RoboDK station: M900-600 working.rdk

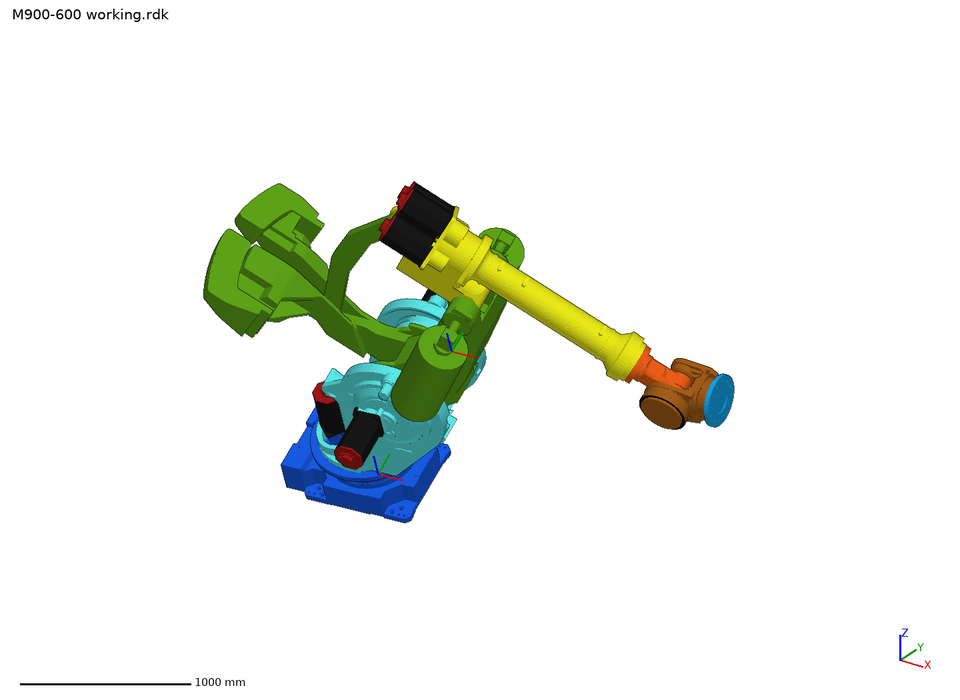
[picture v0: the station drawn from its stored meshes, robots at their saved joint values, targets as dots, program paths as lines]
Station M900-600 working (saved by RoboDK 5.6.0). Poses are relative to the parent item; angles as X-Y-Z fixed-axis rotations.
  - frame Base at (0, 0, 0) mm
    - object M900-600 at (0, 0, 0) mm, geometry from M900-600.IGS
      - item type 7 M900-600-0
      - item type 7 M900-600-1
      - item type 7 M900-600-2
      - item type 7 M900-600-3
      - item type 7 M900-600-4
      - item type 7 M900-600-5
      - item type 7 M900-600-6
      - item type 7 M900-600-7
      - item type 7 M900-600-8
      - item type 7 M900-600-9
      - item type 7 M900-600-10
      - item type 7 M900-600-11
      - item type 7 M900-600-12
      - item type 7 M900-600-13
      - item type 7 M900-600-14
      - item type 7 M900-600-15
      - item type 7 M900-600-16
      - item type 7 M900-600-17
      - item type 7 M900-600-18
      - item type 7 M900-600-19
      - item type 7 M900-600-20
      - item type 7 M900-600-21
      - item type 7 M900-600-22
      - item type 7 M900-600-23
      - item type 7 M900-600-24
      - item type 7 M900-600-25
      - item type 7 M900-600-27
      - item type 7 M900-600-28
      - item type 7 M900-600-29
      - item type 7 M900-600-30
      - item type 7 M900-600-31
      - item type 7 M900-600-32
      - item type 7 M900-600-33
      - item type 7 M900-600-34
      - item type 7 M900-600-35
      - item type 7 M900-600-36
      - item type 7 M900-600-37
      - item type 7 M900-600-38
      - item type 7 M900-600-39
      - item type 7 M900-600-40
      - item type 7 M900-600-41
      - item type 7 M900-600-42
      - item type 7 M900-600-43
      - item type 7 M900-600-44
      - item type 7 M900-600-45
      - item type 7 M900-600-46
      - item type 7 M900-600-47
      - item type 7 M900-600-48
      - item type 7 M900-600-49
      - item type 7 M900-600-50
      - item type 7 M900-600-51
      - item type 7 M900-600-52
      - item type 7 M900-600-53
      - item type 7 M900-600-54
      - item type 7 M900-600-55
      - item type 7 M900-600-56
      - item type 7 M900-600-57
      - item type 7 M900-600-58
      - item type 7 M900-600-59
      - item type 7 M900-600-60
      - item type 7 M900-600-61
      - item type 7 M900-600-62
      - item type 7 M900-600-63
      - item type 7 M900-600-64
      - item type 7 M900-600-65
      - item type 7 M900-600-66
      - item type 7 M900-600-67
      - item type 7 M900-600-68
      - item type 7 M900-600-69
      - item type 7 M900-600-70
      - item type 7 M900-600-71
      - item type 7 M900-600-72
      - item type 7 M900-600-73
      - item type 7 M900-600-74
      - item type 7 M900-600-75
      - item type 7 M900-600-76
      - item type 7 M900-600-77
      - item type 7 M900-600-78
      - item type 7 M900-600-79
      - item type 7 M900-600-80
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      - item type 7 AW: QW | ;W | M900-600-476
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      - item type 7 à': ÿ' | ï' | êÇ | ÿÇ | M900-600-880
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      - item type 7 Ãã: Ãã | M900-600-920
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      - item type 7 ÇE: ÇE | ÇE | M900-600-988
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      - item type 7 èE: èE | èE | M900-600-991
      - item type 7 èE: èE | èE | M900-600-992
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      - item type 7 oE: oE | oE | M900-600-994
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      - item type 7 oE: oE | oE | M900-600-1183
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      - item type 7 oE: oE | oE | oE | oE | oE | M900-600-1188
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      - item type 7 èE: èE | èE | M900-600-1191
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      - item type 7 èE: èE | èE | M900-600-1193
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      - item type 7 ÇE: ÇE | ÇE | M900-600-1210
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      - item type 7 Ã7: Ã7 | Ã7 | Ã7 | M900-600-1705
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      - item type 7 øw: øw | C7 | C7 | C7 | C7 | M900-600-1720
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      - item type 7 M900-600-1759
      - item type 7 M900-600-1760
      - item type 7 M900-600-1761
      - item type 7 M900-600-1762
      - item type 7 M900-600-1763
      - item type 7 M900-600-1764
      - item type 7 M900-600-1765
      - item type 7 M900-600-1766
      - item type 7 M900-600-1767
      - item type 7 M900-600-1768
      - object M900-600-26 at (0, 0, 0) mm, size 824.5 x 687 x 849.8 mm
      - object M900-600-300 at (0, 0, 0) mm, size 1044.1 x 1461.6 x 997.1 mm
      - object M900-600-971 at (0, 0, 0) mm, size 1689.9 x 490 x 569.9 mm
      - object M900-600-1283 at (0, 0, 0) mm, size 408 x 240 x 250 mm
      - object M900-600-1342 at (0, 0, 0) mm, size 421.1 x 354.1 x 306 mm
      - object M900-600-1442 at (0, 0, 0) mm, size 32.1 x 315 x 315 mm
      - object M900-600-1745_Mix at (0, 0, 0) mm, size 1675.1 x 1090.5 x 1519 mm
  - frame M900-600 Base at (1348.37, -10896.16, 0) mm, rotated rx 23.74 ry 1.09 rz 7.57 deg
    - robot M900-600: 6 axes
        modified DH rows (alpha deg, a mm, theta deg, d mm): 0, 0, 0, 1000; -90, 410, -90, 0; 0, 1120, 0, 0; -90, 250, 0, 1285; 90, 0, 0, 0; -90, 0, 180, 300
        joint limits [-180, -77, -80, -360, -122, -360] to [180, 77, 80, 360, 122, 360]; home [0, 0, 0, 0, 0, 0]; saved at [0.804, 32.48, 0.477, 4.209, -33.028, -3.531]
    - frame New M900-600 Base at (0, 1000, 0) mm
      - item type 7 ÿ2: ÿ2 | ÿ6
      - item type 7 ÿ0: þF | éH | @I | ä4 | ÿ! | ÿ1 | jn | °;
      - item type 7 Ãã: Ãã | C7 | C7 | C7 | C7 | Ã7 | Ã7 | Ã7 | Ã7 | D¿ | E¿ | E¿ | D¿
      - item type 7 ÇE: ÇE | ÇE¿ | èE | èE | èE | èE | èE | èE | oE¿ | oE | oE
      - item type 7 M900-600 4
      - item type 7 M900-600 5
      - item type 7 M900-600 6
    - frame New M900-600 Base at (0, 1000, 0) mm
      - item type 7 ÿ2: ÿ2 | ÿ6
      - item type 7 ÿ0: @I | ÿ! | ÿ1 | jn
      - item type 7 Ãã: Ãã | C7 | C7 | C7 | C7 | Ã7 | Ã7 | Ã7 | Ã7
      - item type 7 ÇE: ÇE | ÇE | èE | èE | èE | èE | èE | èE | oE | oE | oE | E¿ | E¿ | E¿ | E¿ | E¿ | E¿ | E¿ | E¿ | E¿ | E¿ | E¿ | E¿ | E¿ | E¿ | E¿ | E¿ | CË | CË | CË
      - item type 7 M900-600 4
      - item type 7 M900-600 5
      - item type 7 Dd: Dd | Dd | Dd | Dd | Dd | M900-600 6
